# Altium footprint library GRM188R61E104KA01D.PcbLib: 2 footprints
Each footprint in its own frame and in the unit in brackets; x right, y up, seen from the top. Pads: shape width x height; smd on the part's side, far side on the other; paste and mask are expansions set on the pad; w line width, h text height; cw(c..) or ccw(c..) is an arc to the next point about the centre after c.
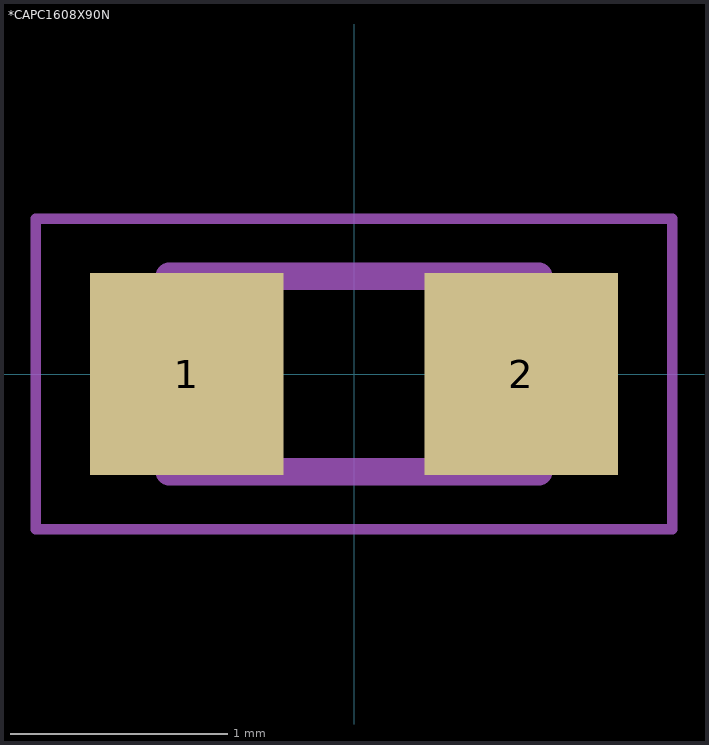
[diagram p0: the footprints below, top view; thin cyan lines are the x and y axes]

## *CAPC1608X90N [mm]
pads (2):
  rect 0.89x0.93 smd: 1(-0.77,0) 2(0.77,0)
Mechanical 13:
  lines w0.127: -0.85,-0.45 -0.85,0.45 ; -0.85,-0.45 0.85,-0.45 ; -0.85,-0.45 -0.85,0.45 ; -0.85,-0.45 0.85,-0.45 ; -0.85,0.45 0.85,0.45 ; -0.85,0.45 0.85,0.45 ; 0.85,-0.45 0.85,0.45 ; 0.85,-0.45 0.85,0.45
Mechanical 15:
  lines w0.05: -1.465,-0.715 -1.465,0.715 1.465,0.715 1.465,-0.715 -1.465,-0.715

## PCBComponent_1 [mm]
